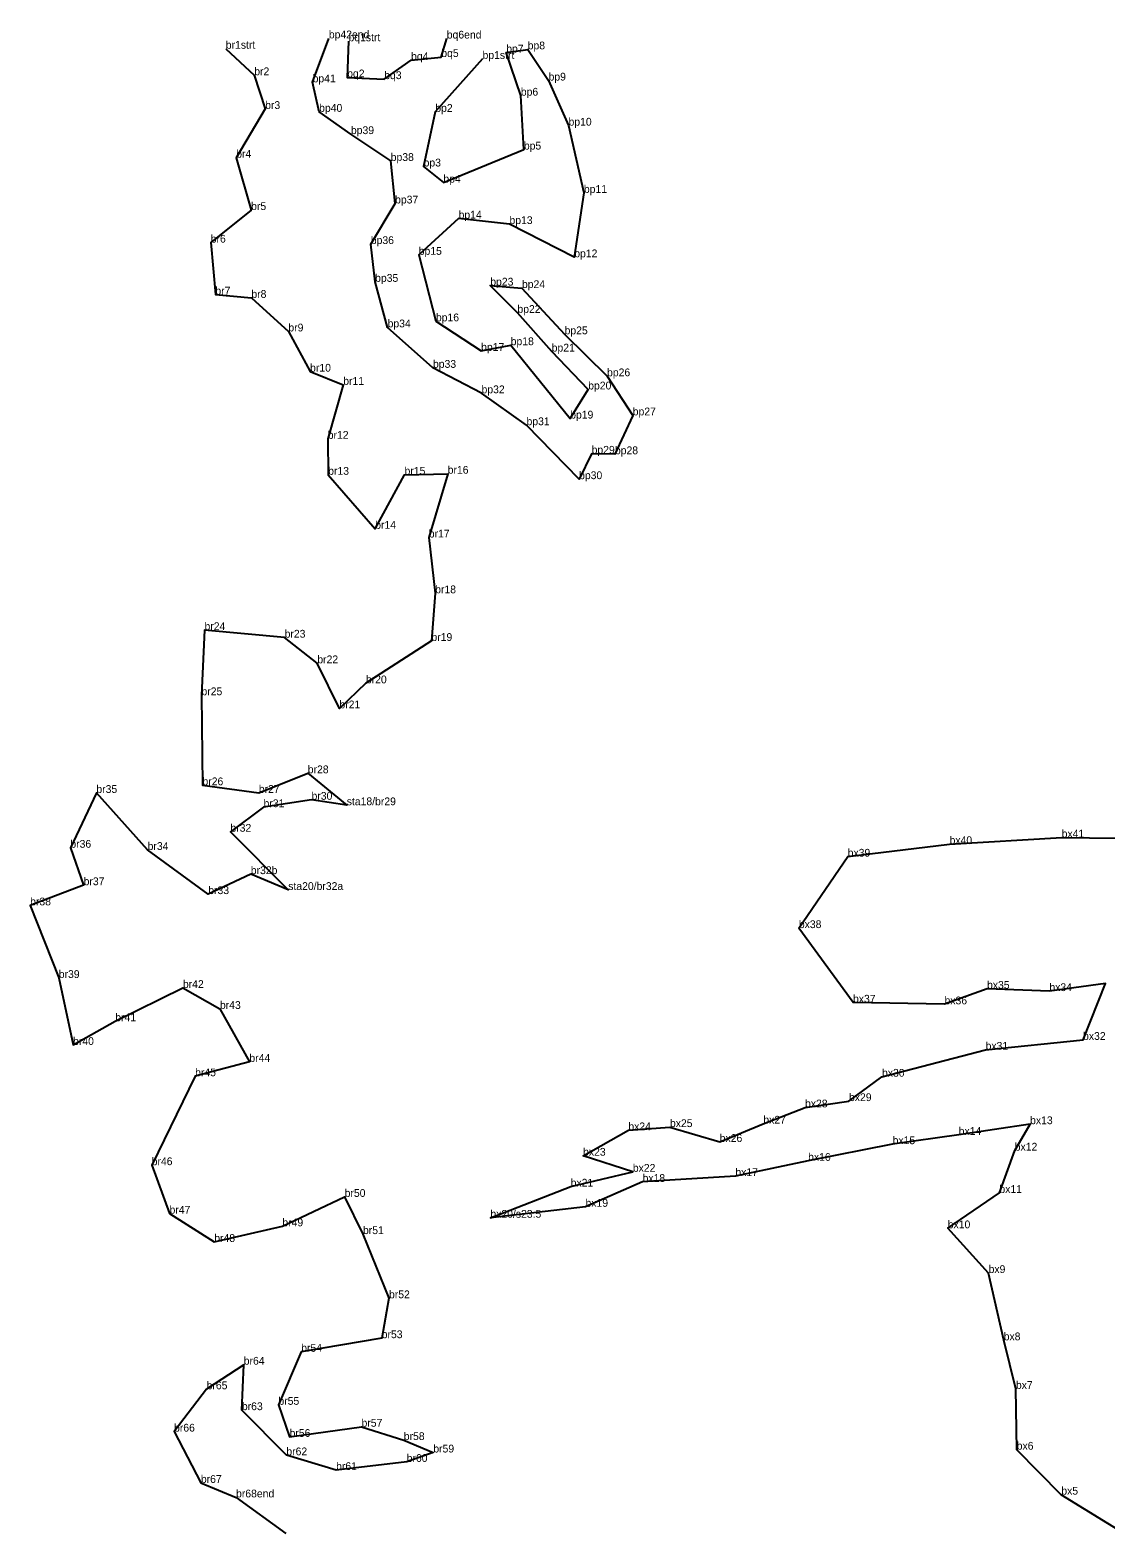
# Model space of a CAD drawing. Extents: x 2072529 to 2267990, y 436423 to 470008.
# Drawn here: x 2233020 to 2233850, y 437812 to 438975 of the extents above; entities that cross this region are included whole.
import ezdxf

# ---------------------------------------------------------------- set-up
doc = ezdxf.new("R2010")
doc.units = 0
doc.layers.add('Level 3', color=7, linetype='Continuous')
doc.layers.add('Old_Level_52', color=7, linetype='Continuous')

msp = doc.modelspace()

# ---------------------------------------------------------------- linework, layer by layer
at = {"layer": 'Level 3'}
for p, q in [((2233171.058, 438960.351), (2233171.058, 438960.351)), ((2233250.54, 438968.368), (2233250.54, 438968.368)), ((2233265.722, 438966.153), (2233265.722, 438966.153)), ((2233341.514, 438968.223), (2233341.514, 438968.223)), ((2233387.354, 438957.417), (2233387.354, 438957.417)), ((2233403.912, 438959.866), (2233403.912, 438959.866)), ((2233313.999, 438951.546), (2233313.999, 438951.546)), ((2233337.277, 438953.96), (2233337.277, 438953.96)), ((2233369.084, 438952.484), (2233369.084, 438952.484)), ((2233193.012, 438939.927), (2233193.012, 438939.927)), ((2233238.028, 438934.445), (2233238.028, 438934.445)), ((2233264.693, 438938.286), (2233264.693, 438938.286)), ((2233293.262, 438936.923), (2233293.262, 438936.923)), ((2233420.007, 438935.811), (2233420.007, 438935.811)), ((2233398.611, 438924.169), (2233398.611, 438924.169)), ((2233201.424, 438913.897), (2233201.424, 438913.897)), ((2233243.053, 438911.718), (2233243.053, 438911.718)), ((2233332.653, 438911.674), (2233332.653, 438911.674)), ((2233435.402, 438901.032), (2233435.402, 438901.032)), ((2233267.568, 438894.505), (2233267.568, 438894.505)), ((2233179.099, 438876.325), (2233179.099, 438876.325)), ((2233400.966, 438882.567), (2233400.966, 438882.567)), ((2233298.26, 438873.801), (2233298.26, 438873.801)), ((2233323.625, 438869.522), (2233323.625, 438869.522)), ((2233338.88, 438857.064), (2233338.88, 438857.064)), ((2233301.659, 438841.001), (2233301.659, 438841.001)), ((2233447.245, 438849.142), (2233447.245, 438849.142)), ((2233190.601, 438835.952), (2233190.601, 438835.952)), ((2233350.609, 438829.324), (2233350.609, 438829.324)), ((2233389.864, 438825.117), (2233389.864, 438825.117)), ((2233159.429, 438810.809), (2233159.429, 438810.809)), ((2233282.914, 438809.689), (2233282.914, 438809.689)), ((2233319.872, 438801.388), (2233319.872, 438801.388)), ((2233439.817, 438799.483), (2233439.817, 438799.483)), ((2233286.242, 438780.557), (2233286.242, 438780.557)), ((2233375.063, 438777.665), (2233375.063, 438777.665)), ((2233399.495, 438775.737), (2233399.495, 438775.737)), ((2233163.015, 438770.697), (2233163.015, 438770.697)), ((2233190.8, 438768.172), (2233190.8, 438768.172)), ((2233333.112, 438750.109), (2233333.112, 438750.109)), ((2233395.99, 438756.593), (2233395.99, 438756.593)), ((2233219.337, 438742.292), (2233219.337, 438742.292)), ((2233295.86, 438745.435), (2233295.86, 438745.435)), ((2233432.367, 438740.095), (2233432.367, 438740.095)), ((2233368.001, 438727.299), (2233368.001, 438727.299)), ((2233390.805, 438731.689), (2233390.805, 438731.689)), ((2233422.421, 438726.764), (2233422.421, 438726.764)), ((2233330.864, 438714.212), (2233330.864, 438714.212)), ((2233236.091, 438711.257), (2233236.091, 438711.257)), ((2233261.633, 438701.078), (2233261.633, 438701.078)), ((2233465.139, 438707.705), (2233465.139, 438707.705)), ((2233368.313, 438694.596), (2233368.313, 438694.596)), ((2233450.581, 438697.522), (2233450.581, 438697.522)), ((2233403.011, 438669.957), (2233403.011, 438669.957)), ((2233436.707, 438675.091), (2233436.707, 438675.091)), ((2233484.94, 438677.54), (2233484.94, 438677.54)), ((2233249.693, 438659.447), (2233249.693, 438659.447)), ((2233453.224, 438647.979), (2233453.224, 438647.979)), ((2233471.201, 438647.572), (2233471.201, 438647.572)), ((2233250.028, 438631.711), (2233250.028, 438631.711)), ((2233308.925, 438631.758), (2233308.925, 438631.758)), ((2233342.212, 438632.512), (2233342.212, 438632.512)), ((2233443.579, 438628.34), (2233443.579, 438628.34)), ((2233286.303, 438590.049), (2233286.303, 438590.049)), ((2233327.623, 438583.344), (2233327.623, 438583.344)), ((2233332.548, 438540.298), (2233332.548, 438540.298)), ((2233154.634, 438511.906), (2233154.634, 438511.906)), ((2233216.434, 438506.06), (2233216.434, 438506.06)), ((2233329.678, 438503.54), (2233329.678, 438503.54)), ((2233241.656, 438486.323), (2233241.656, 438486.323)), ((2233279.123, 438470.844), (2233279.123, 438470.844)), ((2233152.309, 438461.639), (2233152.309, 438461.639)), ((2233258.712, 438451.546), (2233258.712, 438451.546)), ((2233234.306, 438401.459), (2233234.306, 438401.459)), ((2233153.079, 438392.206), (2233153.079, 438392.206)), ((2233071.236, 438386.296), (2233071.236, 438386.296)), ((2233196.547, 438386.332), (2233196.547, 438386.332)), ((2233237.196, 438381.029), (2233237.196, 438381.029)), ((2233264.347, 438376.794), (2233264.347, 438376.794)), ((2233200.165, 438375.307), (2233200.165, 438375.307)), ((2233174.653, 438356.346), (2233174.653, 438356.346)), ((2233051.164, 438343.999), (2233051.164, 438343.999)), ((2233110.769, 438342.307), (2233110.769, 438342.307)), ((2233729.33, 438346.824), (2233729.33, 438346.824)), ((2233815.783, 438351.891), (2233815.783, 438351.891)), ((2233650.735, 438337.127), (2233650.735, 438337.127)), ((2233190.348, 438323.661), (2233190.348, 438323.661)), ((2233061.401, 438315.116), (2233061.401, 438315.116)), ((2233157.542, 438308.254), (2233157.542, 438308.254)), ((2233219.222, 438311.431), (2233219.222, 438311.431)), ((2233020.165, 438299.546), (2233020.165, 438299.546)), ((2233613.074, 438282.026), (2233613.074, 438282.026)), ((2233042.25, 438243.548), (2233042.25, 438243.548)), ((2233137.988, 438235.835), (2233137.988, 438235.835)), ((2233849.586, 438239.379), (2233849.586, 438239.379)), ((2233654.832, 438224.518), (2233654.832, 438224.518)), ((2233758.213, 438235.225), (2233758.213, 438235.225)), ((2233806.317, 438233.443), (2233806.317, 438233.443)), ((2233166.541, 438219.69), (2233166.541, 438219.69)), ((2233725.423, 438223.219), (2233725.423, 438223.219)), ((2233085.811, 438210.206), (2233085.811, 438210.206)), ((2233053.274, 438191.857), (2233053.274, 438191.857)), ((2233832.278, 438195.789), (2233832.278, 438195.789)), ((2233189.252, 438178.835), (2233189.252, 438178.835)), ((2233757.1, 438188.175), (2233757.1, 438188.175)), ((2233147.413, 438167.711), (2233147.413, 438167.711)), ((2233677.193, 438167.39), (2233677.193, 438167.39)), ((2233617.818, 438143.715), (2233617.818, 438143.715)), ((2233651.735, 438148.581), (2233651.735, 438148.581)), ((2233585.632, 438131.162), (2233585.632, 438131.162)), ((2233481.561, 438126.076), (2233481.561, 438126.076)), ((2233513.645, 438128.531), (2233513.645, 438128.531)), ((2233736.361, 438122.504), (2233736.361, 438122.504)), ((2233791.429, 438130.767), (2233791.429, 438130.767)), ((2233552.044, 438117.056), (2233552.044, 438117.056)), ((2233685.392, 438115.355), (2233685.392, 438115.355)), ((2233779.577, 438110.386), (2233779.577, 438110.386)), ((2233113.9, 438099.141), (2233113.9, 438099.141)), ((2233446.658, 438106.446), (2233446.658, 438106.446)), ((2233620.221, 438102.502), (2233620.221, 438102.502)), ((2233485.018, 438094.054), (2233485.018, 438094.054)), ((2233492.531, 438086.244), (2233492.531, 438086.244)), ((2233564.093, 438090.741), (2233564.093, 438090.741)), ((2233262.745, 438074.697), (2233262.745, 438074.697)), ((2233437.067, 438082.609), (2233437.067, 438082.609)), ((2233767.756, 438077.734), (2233767.756, 438077.734)), ((2233127.669, 438061.761), (2233127.669, 438061.761)), ((2233448.518, 438067.024), (2233448.518, 438067.024)), ((2233214.695, 438051.989), (2233214.695, 438051.989)), ((2233375.152, 438058.596), (2233375.152, 438058.596)), ((2233727.919, 438050.466), (2233727.919, 438050.466)), ((2233162.159, 438039.955), (2233162.159, 438039.955)), ((2233276.876, 438045.982), (2233276.876, 438045.982)), ((2233759.41, 438015.958), (2233759.41, 438015.958)), ((2233296.941, 437996.492), (2233296.941, 437996.492)), ((2233291.316, 437965.694), (2233291.316, 437965.694)), ((2233771.054, 437964.06), (2233771.054, 437964.06)), ((2233184.904, 437945.253), (2233184.904, 437945.253)), ((2233229.22, 437955.214), (2233229.22, 437955.214)), ((2233156.281, 437926.296), (2233156.281, 437926.296)), ((2233780.479, 437926.565), (2233780.479, 437926.565)), ((2233211.664, 437914.318), (2233211.664, 437914.318)), ((2233183.475, 437910.178), (2233183.475, 437910.178)), ((2233131.141, 437893.648), (2233131.141, 437893.648)), ((2233220.261, 437889.555), (2233220.261, 437889.555)), ((2233275.761, 437897.369), (2233275.761, 437897.369)), ((2233308.355, 437887.123), (2233308.355, 437887.123)), ((2233217.77, 437875.366), (2233217.77, 437875.366)), ((2233331.108, 437877.515), (2233331.108, 437877.515)), ((2233781.106, 437879.677), (2233781.106, 437879.677)), ((2233256.167, 437863.978), (2233256.167, 437863.978)), ((2233310.594, 437870.249), (2233310.594, 437870.249)), ((2233151.845, 437854.061), (2233151.845, 437854.061)), ((2233178.977, 437842.87), (2233178.977, 437842.87)), ((2233815.486, 437844.975), (2233815.486, 437844.975))]:
    msp.add_line(p, q, dxfattribs=at)
at = {"layer": 'Old_Level_52'}
for points in [[(2233171.058, 438960.351), (2233193.012, 438939.927), (2233201.424, 438913.897), (2233179.099, 438876.325), (2233190.601, 438835.952), (2233159.429, 438810.809), (2233163.015, 438770.697), (2233190.8, 438768.172), (2233219.337, 438742.292), (2233236.091, 438711.257), (2233261.633, 438701.078), (2233249.693, 438659.447), (2233250.028, 438631.711), (2233286.303, 438590.049), (2233308.925, 438631.758), (2233342.212, 438632.512), (2233327.623, 438583.344), (2233332.548, 438540.298), (2233329.678, 438503.54), (2233279.123, 438470.844), (2233258.712, 438451.546), (2233241.656, 438486.323), (2233216.434, 438506.06), (2233154.634, 438511.906), (2233152.309, 438461.639), (2233153.079, 438392.206), (2233196.547, 438386.332), (2233234.306, 438401.459), (2233264.347, 438376.794), (2233237.196, 438381.029), (2233200.165, 438375.307), (2233174.653, 438356.346), (2233219.222, 438311.431), (2233190.348, 438323.661), (2233157.542, 438308.254), (2233110.769, 438342.307), (2233071.236, 438386.296), (2233051.164, 438343.999), (2233061.401, 438315.116), (2233020.165, 438299.546), (2233042.25, 438243.548), (2233053.274, 438191.857), (2233085.811, 438210.206), (2233137.988, 438235.835), (2233166.541, 438219.69), (2233189.252, 438178.835), (2233147.413, 438167.711), (2233113.9, 438099.141), (2233127.669, 438061.761), (2233162.159, 438039.955), (2233214.695, 438051.989), (2233262.745, 438074.697), (2233276.876, 438045.982), (2233296.941, 437996.492), (2233291.316, 437965.694), (2233229.22, 437955.214), (2233211.664, 437914.318), (2233220.261, 437889.555), (2233275.761, 437897.369), (2233308.355, 437887.123), (2233331.108, 437877.515), (2233310.594, 437870.249), (2233256.167, 437863.978), (2233217.77, 437875.366), (2233183.475, 437910.178), (2233184.904, 437945.253), (2233156.281, 437926.296), (2233131.141, 437893.648), (2233151.845, 437854.061), (2233178.977, 437842.87), (2233217.258, 437814.974)], [(2233369.084, 438952.484), (2233332.653, 438911.674), (2233323.625, 438869.522), (2233338.88, 438857.064), (2233400.966, 438882.567), (2233398.611, 438924.169), (2233387.354, 438957.417), (2233403.912, 438959.866), (2233420.007, 438935.811), (2233435.402, 438901.032), (2233447.245, 438849.142), (2233439.817, 438799.483), (2233389.864, 438825.117), (2233350.609, 438829.324), (2233319.872, 438801.388), (2233333.112, 438750.109), (2233368.001, 438727.299), (2233390.805, 438731.689), (2233436.707, 438675.091), (2233450.581, 438697.522), (2233422.421, 438726.764), (2233395.99, 438756.593), (2233375.063, 438777.665), (2233399.495, 438775.737), (2233432.367, 438740.095), (2233465.139, 438707.705), (2233484.94, 438677.54), (2233471.201, 438647.572), (2233453.224, 438647.979), (2233443.579, 438628.34), (2233403.011, 438669.957), (2233368.313, 438694.596), (2233330.864, 438714.212), (2233295.86, 438745.435), (2233286.242, 438780.557), (2233282.914, 438809.689), (2233301.659, 438841.001), (2233298.26, 438873.801), (2233267.568, 438894.505), (2233243.053, 438911.718), (2233238.028, 438934.445), (2233250.54, 438968.368)], [(2233265.722, 438966.153), (2233264.693, 438938.286), (2233293.262, 438936.923), (2233313.999, 438951.546), (2233337.277, 438953.96), (2233341.514, 438968.223)], [(2233869.258, 437811.672), (2233815.486, 437844.975), (2233781.106, 437879.677), (2233780.479, 437926.565), (2233771.054, 437964.06), (2233759.41, 438015.958), (2233727.919, 438050.466), (2233767.756, 438077.734), (2233779.577, 438110.386), (2233791.429, 438130.767), (2233736.361, 438122.504), (2233685.392, 438115.355), (2233620.221, 438102.502), (2233564.093, 438090.741), (2233492.531, 438086.244), (2233448.518, 438067.024), (2233375.152, 438058.596), (2233437.067, 438082.609), (2233485.018, 438094.054), (2233446.658, 438106.446), (2233481.561, 438126.076), (2233513.645, 438128.531), (2233552.044, 438117.056), (2233585.632, 438131.162), (2233617.818, 438143.715), (2233651.735, 438148.581), (2233677.193, 438167.39), (2233757.1, 438188.175), (2233832.278, 438195.789), (2233849.586, 438239.379), (2233806.317, 438233.443), (2233758.213, 438235.225), (2233725.423, 438223.219), (2233654.832, 438224.518), (2233613.074, 438282.026), (2233650.735, 438337.127), (2233729.33, 438346.824), (2233815.783, 438351.891), (2233858.656, 438351.453)]]:
    msp.add_lwpolyline(points, dxfattribs=at)

# ---------------------------------------------------------------- texts
for s, p in [('bp42end', (2233250.54, 438968.368)), ('bq1strt', (2233265.722, 438966.153)), ('bq6end', (2233341.514, 438968.223)), ('br1strt', (2233171.058, 438960.351)), ('bq4', (2233313.999, 438951.546)), ('bq5', (2233337.277, 438953.96)), ('bp1strt', (2233369.084, 438952.484)), ('bp7', (2233387.354, 438957.417)), ('bp8', (2233403.912, 438959.866)), ('br2', (2233193.012, 438939.927)), ('bp41', (2233238.028, 438934.445)), ('bq2', (2233264.693, 438938.286)), ('bq3', (2233293.262, 438936.923)), ('bp9', (2233420.007, 438935.811)), ('bp6', (2233398.611, 438924.169)), ('br3', (2233201.424, 438913.897)), ('bp40', (2233243.053, 438911.718)), ('bp2', (2233332.653, 438911.674)), ('bp39', (2233267.568, 438894.505)), ('bp10', (2233435.402, 438901.032)), ('bp5', (2233400.966, 438882.567)), ('br4', (2233179.099, 438876.325)), ('bp38', (2233298.26, 438873.801)), ('bp3', (2233323.625, 438869.522)), ('bp4', (2233338.88, 438857.064)), ('bp11', (2233447.245, 438849.142)), ('br5', (2233190.601, 438835.952)), ('bp37', (2233301.659, 438841.001)), ('bp14', (2233350.609, 438829.324)), ('bp13', (2233389.864, 438825.117)), ('br6', (2233159.429, 438810.809)), ('bp36', (2233282.914, 438809.689)), ('bp15', (2233319.872, 438801.388)), ('bp12', (2233439.817, 438799.483)), ('bp35', (2233286.242, 438780.557)), ('bp23', (2233375.063, 438777.665)), ('br7', (2233163.015, 438770.697)), ('br8', (2233190.8, 438768.172)), ('bp24', (2233399.495, 438775.737)), ('bp22', (2233395.99, 438756.593)), ('br9', (2233219.337, 438742.292)), ('bp34', (2233295.86, 438745.435)), ('bp16', (2233333.112, 438750.109)), ('bp18', (2233390.805, 438731.689)), ('bp25', (2233432.367, 438740.095)), ('bp17', (2233368.001, 438727.299)), ('bp21', (2233422.421, 438726.764)), ('br10', (2233236.091, 438711.257)), ('bp33', (2233330.864, 438714.212)), ('bp26', (2233465.139, 438707.705)), ('br11', (2233261.633, 438701.078)), ('bp20', (2233450.581, 438697.522)), ('bp32', (2233368.313, 438694.596)), ('bp19', (2233436.707, 438675.091)), ('bp27', (2233484.94, 438677.54)), ('bp31', (2233403.011, 438669.957)), ('br12', (2233249.693, 438659.447)), ('bp29', (2233453.224, 438647.979)), ('bp28', (2233471.201, 438647.572)), ('br13', (2233250.028, 438631.711)), ('br15', (2233308.925, 438631.758)), ('br16', (2233342.212, 438632.512)), ('bp30', (2233443.579, 438628.34)), ('br14', (2233286.303, 438590.049)), ('br17', (2233327.623, 438583.344)), ('br18', (2233332.548, 438540.298)), ('br24', (2233154.634, 438511.906)), ('br23', (2233216.434, 438506.06)), ('br19', (2233329.678, 438503.54)), ('br22', (2233241.656, 438486.323)), ('br20', (2233279.123, 438470.844)), ('br25', (2233152.309, 438461.639)), ('br21', (2233258.712, 438451.546)), ('br28', (2233234.306, 438401.459)), ('br35', (2233071.236, 438386.296)), ('br26', (2233153.079, 438392.206)), ('br27', (2233196.547, 438386.332)), ('br30', (2233237.196, 438381.029)), ('br31', (2233200.165, 438375.307)), ('sta18/br29', (2233264.347, 438376.794)), ('br32', (2233174.653, 438356.346)), ('bx40', (2233729.33, 438346.824)), ('bx41', (2233815.783, 438351.891)), ('br36', (2233051.164, 438343.999)), ('br34', (2233110.769, 438342.307)), ('bx39', (2233650.735, 438337.127)), ('br32b', (2233190.348, 438323.661)), ('br37', (2233061.401, 438315.116)), ('sta20/br32a', (2233219.222, 438311.431)), ('br38', (2233020.165, 438299.546)), ('br33', (2233157.542, 438308.254)), ('bx38', (2233613.074, 438282.026)), ('br39', (2233042.25, 438243.548)), ('br42', (2233137.988, 438235.835)), ('bx35', (2233758.213, 438235.225)), ('bx34', (2233806.317, 438233.443)), ('br43', (2233166.541, 438219.69)), ('bx37', (2233654.832, 438224.518)), ('bx36', (2233725.423, 438223.219)), ('br41', (2233085.811, 438210.206)), ('bx32', (2233832.278, 438195.789)), ('br40', (2233053.274, 438191.857)), ('bx31', (2233757.1, 438188.175)), ('br44', (2233189.252, 438178.835)), ('br45', (2233147.413, 438167.711)), ('bx30', (2233677.193, 438167.39)), ('bx29', (2233651.735, 438148.581)), ('bx28', (2233617.818, 438143.715)), ('bx24', (2233481.561, 438126.076)), ('bx25', (2233513.645, 438128.531)), ('bx27', (2233585.632, 438131.162)), ('bx13', (2233791.429, 438130.767)), ('bx26', (2233552.044, 438117.056)), ('bx15', (2233685.392, 438115.355)), ('bx14', (2233736.361, 438122.504)), ('bx23', (2233446.658, 438106.446)), ('bx16', (2233620.221, 438102.502)), ('bx12', (2233779.577, 438110.386)), ('br46', (2233113.9, 438099.141)), ('bx22', (2233485.018, 438094.054)), ('bx17', (2233564.093, 438090.741)), ('bx21', (2233437.067, 438082.609)), ('bx18', (2233492.531, 438086.244)), ('br50', (2233262.745, 438074.697)), ('bx19', (2233448.518, 438067.024)), ('bx11', (2233767.756, 438077.734)), ('br47', (2233127.669, 438061.761)), ('bx20/s23.5', (2233375.152, 438058.596)), ('br49', (2233214.695, 438051.989)), ('br51', (2233276.876, 438045.982)), ('bx10', (2233727.919, 438050.466)), ('br48', (2233162.159, 438039.955)), ('bx9', (2233759.41, 438015.958)), ('br52', (2233296.941, 437996.492)), ('br53', (2233291.316, 437965.694)), ('bx8', (2233771.054, 437964.06)), ('br54', (2233229.22, 437955.214)), ('br64', (2233184.904, 437945.253)), ('br65', (2233156.281, 437926.296)), ('bx7', (2233780.479, 437926.565)), ('br63', (2233183.475, 437910.178)), ('br55', (2233211.664, 437914.318)), ('br66', (2233131.141, 437893.648)), ('br57', (2233275.761, 437897.369)), ('br56', (2233220.261, 437889.555)), ('br58', (2233308.355, 437887.123)), ('br62', (2233217.77, 437875.366)), ('br60', (2233310.594, 437870.249)), ('br59', (2233331.108, 437877.515)), ('bx6', (2233781.106, 437879.677)), ('br61', (2233256.167, 437863.978)), ('br67', (2233151.845, 437854.061)), ('br68end', (2233178.977, 437842.87)), ('bx5', (2233815.486, 437844.975))]:
    msp.add_text(s, height=6).set_placement(p)

doc.saveas('drawing.dxf')
